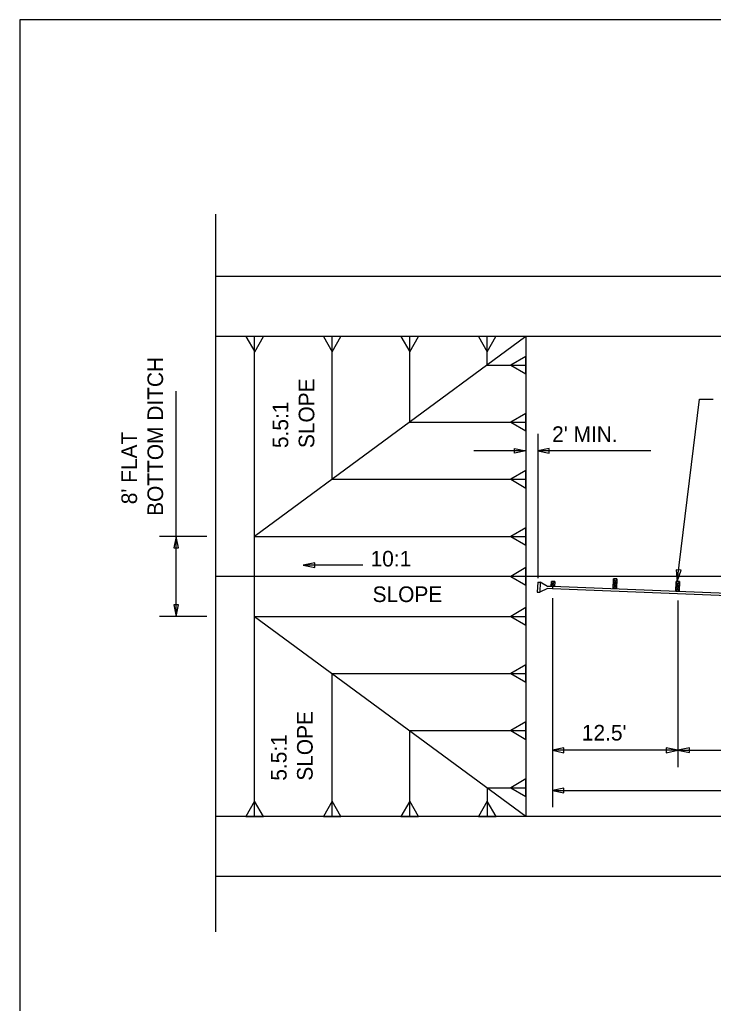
# Model space of a CAD drawing. Extents: x -439.1 to -407.9, y -458.1 to -436.2.
# Drawn here: x -439.11 to -432.45, y -447.12 to -437.68 of the extents above; entities that cross this region are included whole.
import ezdxf

# ---------------------------------------------------------------- set-up
doc = ezdxf.new("R2010")
doc.units = 0
doc.layers.add('Bridge-Named Boundary', color=7, linetype='Continuous')
doc.layers.add('Default', color=7, linetype='Continuous')

msp = doc.modelspace()

# ---------------------------------------------------------------- linework, layer by layer
at = {"layer": 'Bridge-Named Boundary'}
msp.add_lwpolyline([(-439.109, -458.0508), (-407.859, -458.0508), (-407.859, -437.6758), (-439.109, -437.6758)], close=True, dxfattribs=at)
at = {"layer": 'Default'}
for p, q in [((-437.226, -446.4363), (-437.226, -439.5433)), ((-410.372, -440.1433), (-437.226, -440.1433)), ((-410.372, -440.7193), (-437.226, -440.7193)), ((-436.854, -445.3273), (-436.854, -440.7193)), ((-434.25, -440.7193), (-436.854, -442.6393)), ((-436.11, -442.0908), (-436.11, -440.7193)), ((-435.366, -441.5422), (-435.366, -440.7193)), ((-434.622, -440.9936), (-434.622, -440.7193)), ((-434.25, -440.7193), (-434.25, -445.3273)), ((-434.622, -440.9936), (-434.25, -440.9936)), ((-437.6065, -442.6394), (-437.6065, -441.2429)), ((-432.7973, -443.0714), (-432.5853, -441.3194)), ((-432.5853, -441.3194), (-432.4532, -441.3194)), ((-435.366, -441.5422), (-434.25, -441.5422)), ((-434.137, -441.6553), (-434.137, -443.0415)), ((-434.25, -441.8165), (-434.7487, -441.8165)), ((-433.0501, -441.8165), (-434.137, -441.8165)), ((-436.11, -442.0908), (-434.25, -442.0908)), ((-437.3133, -442.6394), (-437.7677, -442.6394)), ((-437.6065, -443.4074), (-437.6065, -442.6394)), ((-436.854, -442.6393), (-434.25, -442.6393)), ((-435.8143, -442.9149), (-436.3881, -442.9149)), ((-434.25, -443.0233), (-437.2218, -443.0233)), ((-413.348, -443.0233), (-434.25, -443.0233)), ((-434.137, -443.0773), (-434.141, -443.1733)), ((-434.137, -443.0773), (-434.113, -443.0783)), ((-434.113, -443.0783), (-434.117, -443.1743)), ((-434.043, -443.1203), (-434.113, -443.0783)), ((-433.995, -443.1193), (-434.043, -443.1203)), ((-434.007, -443.1193), (-434.005, -443.0713)), ((-434.007, -443.1193), (-433.973, -443.0723)), ((-433.975, -443.1203), (-434.007, -443.1193)), ((-433.973, -443.0723), (-434.005, -443.0713)), ((-433.975, -443.1203), (-434.005, -443.0713)), ((-433.995, -443.1193), (-433.996, -443.1433)), ((-424.999, -443.4793), (-433.995, -443.1193)), ((-433.973, -443.0723), (-433.975, -443.1203)), ((-433.412, -443.1429), (-433.4086, -443.047)), ((-433.412, -443.1429), (-433.3783, -443.0961)), ((-433.3767, -443.0481), (-433.4103, -443.0949)), ((-433.3783, -443.0961), (-433.4103, -443.0949)), ((-433.4103, -443.0949), (-433.38, -443.144)), ((-433.3767, -443.0481), (-433.4086, -443.047)), ((-433.3783, -443.0961), (-433.4086, -443.047)), ((-433.3767, -443.0481), (-433.38, -443.144)), ((-433.3766, -443.0481), (-433.3766, -443.0481)), ((-432.8125, -443.1669), (-432.8091, -443.071)), ((-432.8125, -443.1669), (-432.7788, -443.12)), ((-432.7771, -443.0721), (-432.8108, -443.1189)), ((-432.7788, -443.12), (-432.8108, -443.1189)), ((-432.8108, -443.1189), (-432.7805, -443.168)), ((-432.7771, -443.0721), (-432.8091, -443.071)), ((-432.7788, -443.12), (-432.8091, -443.071)), ((-432.7771, -443.0721), (-432.7805, -443.168)), ((-432.7771, -443.0721), (-432.7771, -443.0721)), ((-434.141, -443.1733), (-434.117, -443.1743)), ((-434.043, -443.1383), (-434.117, -443.1743)), ((-433.996, -443.1433), (-434.043, -443.1383)), ((-425, -443.5033), (-433.996, -443.1433)), ((-433.412, -443.1429), (-433.412, -443.1429)), ((-433.38, -443.144), (-433.412, -443.1429)), ((-433.396, -443.1435), (-433.396, -443.1435)), ((-432.8125, -443.1669), (-432.8125, -443.1669)), ((-432.7805, -443.168), (-432.8125, -443.1669)), ((-432.7965, -443.1675), (-432.7965, -443.1675)), ((-433.996, -443.231), (-433.996, -445.2408)), ((-432.7921, -443.2551), (-432.7921, -444.855)), ((-437.3133, -443.4074), (-437.7677, -443.4074)), ((-436.854, -443.4073), (-434.25, -445.3273)), ((-436.854, -443.4073), (-434.25, -443.4073)), ((-436.11, -445.3273), (-436.11, -443.9559)), ((-436.11, -443.9559), (-434.25, -443.9559)), ((-435.366, -445.3273), (-435.366, -444.5045)), ((-435.366, -444.5045), (-434.25, -444.5045)), ((-432.7921, -444.6938), (-433.996, -444.6938)), ((-432.7921, -444.692), (-429.1955, -444.692)), ((-434.622, -445.053), (-434.622, -445.3273)), ((-434.622, -445.053), (-434.25, -445.053)), ((-433.996, -445.0796), (-429.1955, -445.0796)), ((-437.226, -445.3273), (-410.372, -445.3273)), ((-437.226, -445.9033), (-410.372, -445.9033))]:
    msp.add_line(p, q, dxfattribs=at)
for points in [[(-436.77, -440.719), (-436.938, -440.7197), (-436.8534, -440.8648)], [(-436.026, -440.719), (-436.194, -440.7197), (-436.1094, -440.8648)], [(-435.282, -440.719), (-435.45, -440.7197), (-435.3654, -440.8648)], [(-434.538, -440.719), (-434.706, -440.7197), (-434.6214, -440.8648)], [(-434.25, -440.9096), (-434.3954, -440.9936), (-434.25, -441.0776)], [(-434.25, -441.4582), (-434.3954, -441.5422), (-434.25, -441.6262)], [(-434.3606, -441.7935), (-434.25, -441.8165), (-434.3606, -441.8395)], [(-434.0263, -441.7935), (-434.137, -441.8165), (-434.0263, -441.8395)], [(-434.25, -442.0068), (-434.3954, -442.0908), (-434.25, -442.1748)], [(-437.5836, -442.75), (-437.6065, -442.6394), (-437.6295, -442.75)], [(-434.25, -442.5553), (-434.3954, -442.6393), (-434.25, -442.7233)], [(-436.2774, -442.8919), (-436.3881, -442.9149), (-436.2774, -442.9379)], [(-434.25, -442.9393), (-434.3954, -443.0233), (-434.25, -443.1073)], [(-432.8068, -442.9588), (-432.7973, -443.0714), (-432.7612, -442.9643)], [(-437.6295, -443.2967), (-437.6065, -443.4074), (-437.5836, -443.2967)], [(-434.25, -443.3233), (-434.3954, -443.4073), (-434.25, -443.4913)], [(-434.25, -443.8719), (-434.3954, -443.9559), (-434.25, -444.0399)], [(-434.25, -444.4205), (-434.3954, -444.5045), (-434.25, -444.5885)], [(-433.8853, -444.6708), (-433.996, -444.6938), (-433.8853, -444.7167)], [(-432.9028, -444.7167), (-432.7921, -444.6938), (-432.9028, -444.6708)], [(-432.6815, -444.669), (-432.7921, -444.692), (-432.6815, -444.715)], [(-434.25, -444.969), (-434.3954, -445.0531), (-434.25, -445.137)], [(-433.8853, -445.0566), (-433.996, -445.0796), (-433.8853, -445.1026)], [(-436.7695, -445.3287), (-436.8541, -445.1836), (-436.9375, -445.3295)], [(-436.0255, -445.3287), (-436.1101, -445.1836), (-436.1935, -445.3295)], [(-435.2815, -445.3287), (-435.3661, -445.1836), (-435.4495, -445.3295)], [(-434.5375, -445.3287), (-434.6221, -445.1836), (-434.7055, -445.3295)]]:
    msp.add_lwpolyline(points, close=True, dxfattribs=at)

# ---------------------------------------------------------------- texts
for s, p in [('BOTTOM DITCH', (-437.7328, -442.4417)), ('SLOPE', (-436.2813, -441.7908)), ('5.5:1 ', (-436.5313, -441.7908)), ("  8' FLAT", (-437.9828, -442.4417)), ('SLOPE', (-436.2971, -444.9857)), ('5.5:1 ', (-436.5471, -444.9857))]:
    msp.add_text(s, height=0.15, rotation=90, dxfattribs=at).set_placement(p)
for s, p in [("2' MIN.", (-433.9988, -441.7321)), ('10:1', (-435.7413, -442.928)), ('SLOPE', (-435.7221, -443.2696)), ("12.5'", (-433.7136, -444.5996))]:
    msp.add_text(s, height=0.15, dxfattribs=at).set_placement(p)

doc.saveas('drawing.dxf')
